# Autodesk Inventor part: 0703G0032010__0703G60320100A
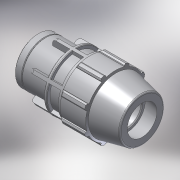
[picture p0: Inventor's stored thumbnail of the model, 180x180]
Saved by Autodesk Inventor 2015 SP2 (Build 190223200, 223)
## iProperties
Created: 2017-02
Part Number: 0703G0032010__0703G60320100A
Material: PVC-Piping
Description: PLASSON FEMALE ADAPTOR G 32-1"
Document SubType Name: Modeling
Designer: KIM
Mass: 92.6774 g
Surface Area: 199.44 cm^2
Volume: 66.1981 cm^3
Density: 1.4 g/cm^3
Appearance: Smooth - White
Author: KIM
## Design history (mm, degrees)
derived "0703G0.ipt"
feature "Solid1::0703G0.ipt"
tag "TaggingFeature1"
body "Solid1"
other parameters: "d2" = 32, "d4" = 12.71429, "d5" = 22.25, "d7" = 64, "d9" = 12.71429, "d11" = 2.54286, "d12" = 51.2, "d13" = 120 deg, "d14" = 48, "d15" = 12 deg, "d16" = 57.6, "d18" = 1.6, "d19" = 35 deg, "d20" = 17.5 deg, "d21" = 59.52, "d23" = 0, "d25" = 360 deg, "d27" = 1.28, "d34" = 3.2, "d35" = 26.7, "d36" = 0, "d42" = 22.25, "d43" = 1.92, "d46" = 0.96, "d49" = 72, "d51" = 89, "d53" = 0.64, "d55" = 360 deg, "d61" = 14, "d62" = 25.6, "d63" = 24.117, "d64" = 29.66667, "d65" = 3.2, "d66" = 0.5, "d67" = 1, "d68" = 7, "d69" = 46.08, "d_" = 32, "E_" = 64, "H_" = 89, "l_" = 72, "l_2" = 14, "Rp_" = 24.117
